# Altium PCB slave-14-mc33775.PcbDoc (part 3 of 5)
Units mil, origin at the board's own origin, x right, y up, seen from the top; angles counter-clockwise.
Board outline 6299.21 x 3937.01 mil, 6 copper layers (Top Copper, Supply, Signal Layer 1, Signal Layer 2, GND, Bot Copper), stack 69.773 mil thick; 428 components, 213 nets, 1149 pads, 1672 vias.
Unrouted connection lines stored in the file: 1.
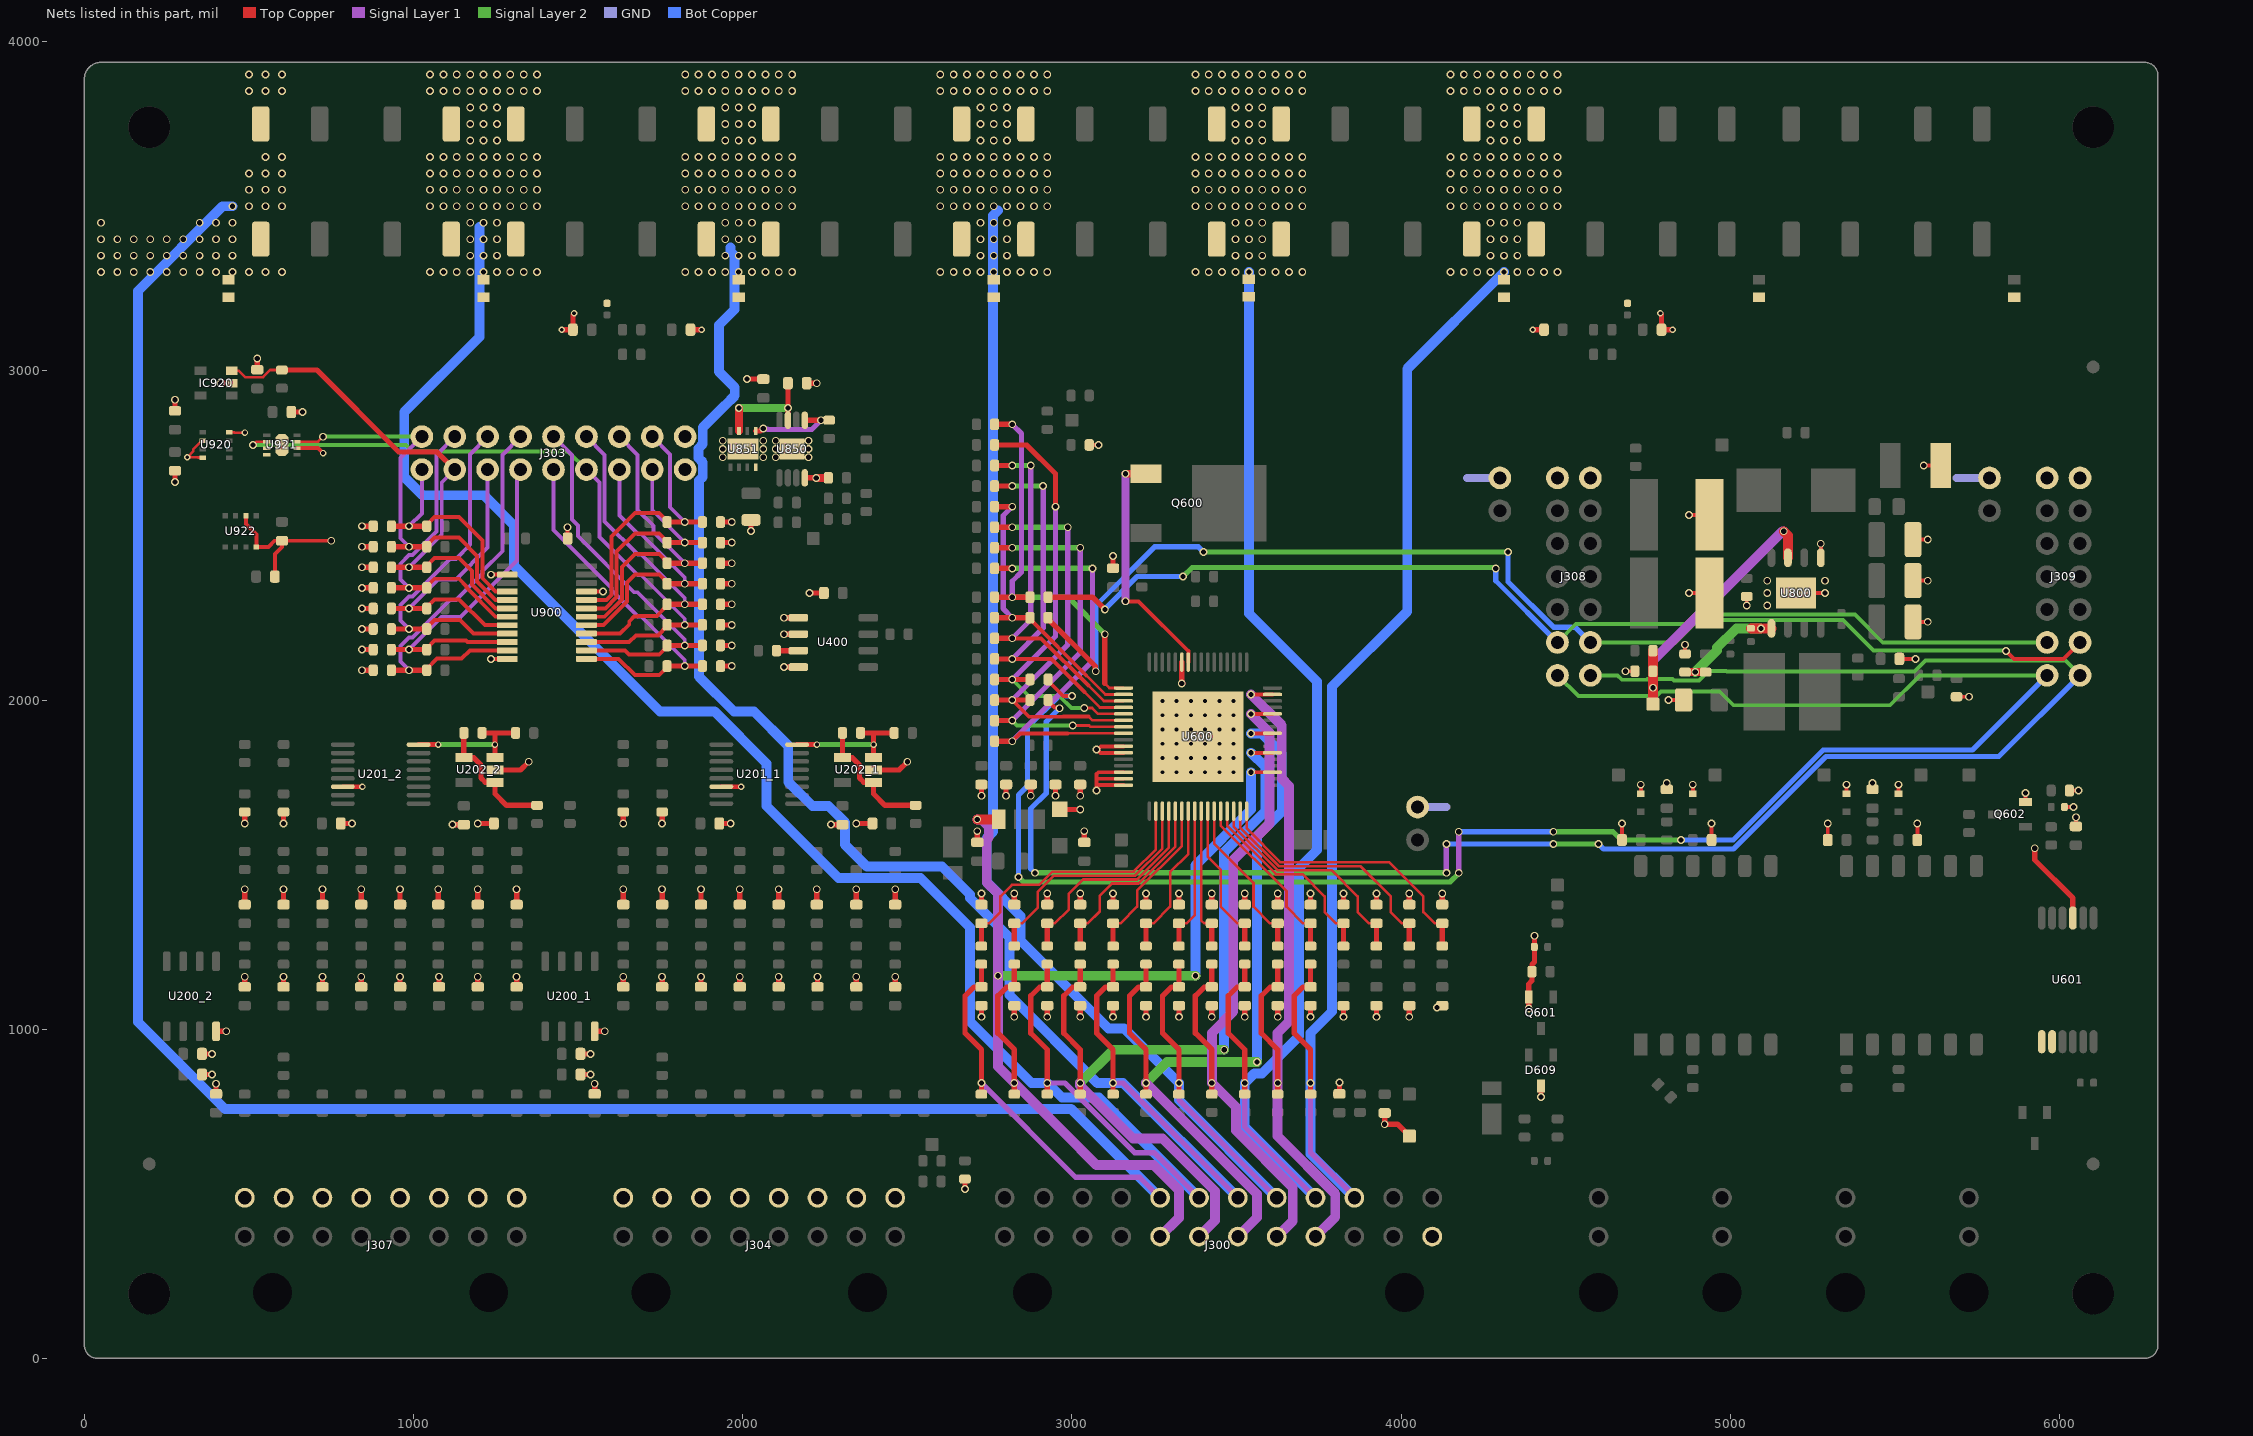
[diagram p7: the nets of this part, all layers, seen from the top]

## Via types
v1: diameter 23.62, hole 15.75, Top Copper to Bot Copper, 1585 vias
v2: diameter 19.68, hole 11.81, Top Copper to Bot Copper, 87 vias

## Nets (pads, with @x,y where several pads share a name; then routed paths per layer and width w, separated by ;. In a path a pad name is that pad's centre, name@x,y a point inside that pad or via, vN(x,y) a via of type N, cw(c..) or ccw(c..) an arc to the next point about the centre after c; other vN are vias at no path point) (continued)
CIN4: C510.2 J300.15 R505.2 R516.1 R708.1 R717.1 R718.2 R731.1 R732.2 | length 3963.7
  Top Copper w16: R516.1@3725,802.56 v1(3725,836.52) 3725,938.04 3675,988.04 3675,1101.24 3702.3,1128.54 C510.2@3725,1128.54 R505.2@3725,1197.44
  Signal Layer 1 w16: v1(3725,836.52) 3725,625 3857.99,492.01 J300.15@3857.99,487.99
  Bot Copper w30: J300.15@3857.99,487.99 3725,620.98 3725,988.27 3790.19,1053.46 3790.19,2040.96 4018.75,2269.52 4018.75,3006.25 v1(4312.5,3300)
  other v1: 4150,3300 4190.62,3300 4231.25,3300 4271.87,3300 4353.12,3300 4393.75,3300 4434.37,3300 4475,3300 4271.87,3350 4312.5,3350 4353.12,3350 4271.87,3400 4312.5,3400 4353.12,3400 4271.87,3450 4312.5,3450 4353.12,3450 4150,3500 4190.62,3500 4231.25,3500 4271.87,3500 4312.5,3500 4353.12,3500 4393.75,3500 4434.37,3500 4475,3500 4150,3550 4190.62,3550 4231.25,3550 4271.87,3550 4312.5,3550 4353.12,3550 4393.75,3550 4434.37,3550 4475,3550 4150,3600 4190.62,3600 4231.25,3600 4271.87,3600 4312.5,3600 4353.12,3600 4393.75,3600 4434.37,3600 4475,3600 4150,3650 4190.62,3650 4231.25,3650 4271.87,3650 4312.5,3650 4353.12,3650 4393.75,3650 4434.37,3650 4475,3650 4271.87,3700 4312.5,3700 4353.12,3700 4271.87,3750 4312.5,3750 4353.12,3750 4271.87,3800 4312.5,3800 4353.12,3800 4150,3850 4190.62,3850 4231.25,3850 4271.87,3850 4312.5,3850 4353.12,3850 4393.75,3850 4434.37,3850 4475,3850 4150,3900 4190.62,3900 4231.25,3900 4271.87,3900 4312.5,3900 4353.12,3900 4393.75,3900 4434.37,3900 4475,3900
CIN5: C506.2 J300.4 R503.2 R517.1 U600.31 | length 2319.5
  Top Copper w12: v1@3545.96,2016.83 U600.31@3609.35,2016.83
  Top Copper w16: R517.1@3625,802.56 v1(3625,836.52) 3625,938.04 3575,988.04 3575,1101.24 3602.3,1128.54 C506.2@3625,1128.54 R503.2@3625,1197.44
  Signal Layer 1 w30: v1(3544.09,2016.83) 3637.5,1923.43 3637.5,1761.7 3659.81,1739.39 3659.81,1023.08 3625,988.27 v1(3625,836.52) 3625,675 3800,500 3800,430 J300.4@3740,370
CIN6: C502.2 J300.16 R501.2 R518.1 R709.1 R719.1 R720.2 R733.1 R734.2 | length 3978.9
  Top Copper w16: R518.1@3525,802.56 v1(3525,836.52) 3525,938.04 3475,988.04 3475,1101.24 3502.3,1128.54 C502.2@3525,1128.54 R501.2@3525,1197.44
  Signal Layer 1 w16: v1(3525,836.52) 3525,702.99 J300.16@3740,487.99
  Bot Copper w30: v1(3537.5,3300) 3537.5,2263.27 3745,2055.77 3745,1544.52 3690.19,1489.71 3690.19,978.46 3576.92,865.19 3553.67,865.19 v1(3525,836.52) 3525,702.99 J300.16@3740,487.99
  other v1: 3375,3300 3415.62,3300 3456.25,3300 3496.87,3300 3578.12,3300 3618.75,3300 3659.37,3300 3700,3300 3496.87,3350 3537.5,3350 3578.12,3350 3496.87,3400 3537.5,3400 3578.12,3400 3496.87,3450 3537.5,3450 3578.12,3450 3375,3500 3415.62,3500 3456.25,3500 3496.87,3500 3537.5,3500 3578.12,3500 3618.75,3500 3659.37,3500 3700,3500 3375,3550 3415.62,3550 3456.25,3550 3496.87,3550 3537.5,3550 3578.12,3550 3618.75,3550 3659.37,3550 3700,3550 3375,3600 3415.62,3600 3456.25,3600 3496.87,3600 3537.5,3600 3578.12,3600 3618.75,3600 3659.37,3600 3700,3600 3375,3650 3415.62,3650 3456.25,3650 3496.87,3650 3537.5,3650 3578.12,3650 3618.75,3650 3659.37,3650 3700,3650 3496.87,3700 3537.5,3700 3578.12,3700 3496.87,3750 3537.5,3750 3578.12,3750 3496.87,3800 3537.5,3800 3578.12,3800 3375,3850 3415.62,3850 3456.25,3850 3496.87,3850 3537.5,3850 3578.12,3850 3618.75,3850 3659.37,3850 3700,3850 3375,3900 3415.62,3900 3456.25,3900 3496.87,3900 3537.5,3900 3578.12,3900 3618.75,3900 3659.37,3900 3700,3900
CIN7: C528.2 J300.5 R514.2 R519.1 U600.28 | length 2319.5
  Top Copper w12: v1@3545.96,1957.78 U600.28@3609.35,1957.78
  Top Copper w16: R519.1@3425,802.56 v1(3425,836.52) 3425,938.04 3375,988.04 3375,1101.24 3402.3,1128.54 C528.2@3425,1128.54 R514.2@3425,1197.44
  Signal Layer 1 w30: v1(3544.09,1957.78) 3600,1901.87 3600,1624.23 3490.19,1514.42 3490.19,1053.46 3425,988.27 v1(3425,836.52) 3498,763.52 3498,691.81 3671.01,518.8 3671.01,417.42 3623.59,370 J300.5@3622.01,370
CIN8: C524.2 J300.17 R512.2 R520.1 R710.1 R721.1 R722.2 R735.1 R736.2 | length 4327.7
  Top Copper w16: R520.1@3325,802.56 v1(3325,836.52) 3325,938.04 3275,988.04 3275,1101.24 3302.3,1128.54 C524.2@3325,1128.54 R512.2@3325,1197.44
  Signal Layer 1 w16: v1(3325,836.52) 3325,785 J300.17@3622.01,487.99
  Bot Copper w30: 2775,3487.5 2759.81,3472.31 2759.81,1599.75 2741.27,1581.21 2741.27,1447 2843.81,1344.46 2843.81,1269.46 3110.58,1002.69 3158.83,1002.69 v1(3325,836.52) 3325,785 J300.17@3622.01,487.99
  other v1: 2600,3300 2640.62,3300 2681.25,3300 2721.87,3300 2762.5,3300 2803.12,3300 2843.75,3300 2884.37,3300 2925,3300 2721.87,3350 2762.5,3350 2803.12,3350 2721.87,3400 2762.5,3400 2803.12,3400 2721.87,3450 2762.5,3450 2803.12,3450 2600,3500 2640.62,3500 2681.25,3500 2721.87,3500 2762.5,3500 2803.12,3500 2843.75,3500 2884.37,3500 2925,3500 2600,3550 2640.62,3550 2681.25,3550 2721.87,3550 2762.5,3550 2803.12,3550 2843.75,3550 2884.37,3550 2925,3550 2600,3600 2640.62,3600 2681.25,3600 2721.87,3600 2762.5,3600 2803.12,3600 2843.75,3600 2884.37,3600 2925,3600 2600,3650 2640.62,3650 2681.25,3650 2721.87,3650 2762.5,3650 2803.12,3650 2843.75,3650 2884.37,3650 2925,3650 2721.87,3700 2762.5,3700 2803.12,3700 2721.87,3750 2762.5,3750 2803.12,3750 2721.87,3800 2762.5,3800 2803.12,3800 2600,3850 2640.62,3850 2681.25,3850 2721.87,3850 2762.5,3850 2803.12,3850 2843.75,3850 2884.37,3850 2925,3850 2600,3900 2640.62,3900 2681.25,3900 2721.87,3900 2762.5,3900 2803.12,3900 2843.75,3900 2884.37,3900 2925,3900
CIN9: C520.2 J300.6 R510.2 R521.1 U600.25 | length 2594.7
  Top Copper w12: v1@3545.96,1898.72 U600.25@3609.35,1898.72
  Top Copper w16: R521.1@3225,802.56 v1(3225,836.52) 3225,938.04 3175,988.04 3175,1101.24 3202.3,1128.54 C520.2@3225,1128.54 R510.2@3225,1197.44
  Signal Layer 1 w30: v1(3225,836.52) 3562.5,499.02 3562.5,428.48 J300.6@3504.02,370
  Signal Layer 2 w30: v1(3225,836.52) 3288.48,900 v1(3562.5,900)
  Bot Copper w30: v1(3544.09,1898.72) 3576.28,1898.72 3637.5,1837.5 3637.5,1661.73 3562.5,1586.73 v1(3562.5,900)
CIN10: C516.2 J300.18 R508.2 R522.1 R711.1 R723.1 R724.2 R737.1 R738.2 | length 4883.5
  Top Copper w16: R522.1@3125,802.56 v1(3125,836.52) 3125,938.04 3075,988.04 3075,1101.24 3102.3,1128.54 C516.2@3125,1128.54 R508.2@3125,1197.44
  Signal Layer 1 w16: v1(3125,836.52) 3155.49,836.52 J300.18@3504.02,487.99
  Bot Copper w30: 1962.5,3375 1962.5,3362.5 1975,3350 1975,3300 1975,3186.73 1927.69,3139.42 1927.69,2997.13 1975.66,2949.16 1975.66,2924.3 1945.77,2894.41 1945.08,2894.41 1878.45,2827.78 1878.45,2777.86 1865.19,2764.6 1865.19,2735.58 1878.45,2722.32 1878.45,2677.86 1867.35,2666.76 1867.35,2070.92 1973.08,1965.19 2034.04,1965.19 2138.16,1861.07 2138.16,1751.42 2211.4,1678.18 2260.62,1678.18 2310.19,1628.61 2310.19,1560.29 2376.66,1493.81 2605.42,1493.81 2690.19,1409.04 2690.19,1398.08 2809.81,1278.46 2809.81,1103.46 3076.75,836.52 v1(3125,836.52) 3155.49,836.52 J300.18@3504.02,487.99
  other v1: 1825,3300 1865.62,3300 1906.25,3300 1946.87,3300 1987.5,3300 2028.12,3300 2068.75,3300 2109.37,3300 2150,3300 1946.87,3350 1987.5,3350 2028.12,3350 1946.87,3400 1987.5,3400 2028.12,3400 1946.87,3450 1987.5,3450 2028.12,3450 1825,3500 1865.62,3500 1906.25,3500 1946.87,3500 1987.5,3500 2028.12,3500 2068.75,3500 2109.37,3500 2150,3500 1825,3550 1865.62,3550 1906.25,3550 1946.87,3550 1987.5,3550 2028.12,3550 2068.75,3550 2109.37,3550 2150,3550 1825,3600 1865.62,3600 1906.25,3600 1946.87,3600 1987.5,3600 2028.12,3600 2068.75,3600 2109.37,3600 2150,3600 1825,3650 1865.62,3650 1906.25,3650 1946.87,3650 1987.5,3650 2028.12,3650 2068.75,3650 2109.37,3650 2150,3650 1946.87,3700 1987.5,3700 2028.12,3700 1946.87,3750 1987.5,3750 2028.12,3750 1946.87,3800 1987.5,3800 2028.12,3800 1825,3850 1865.62,3850 1906.25,3850 1946.87,3850 1987.5,3850 2028.12,3850 2068.75,3850 2109.37,3850 2150,3850 1825,3900 1865.62,3900 1906.25,3900 1946.87,3900 1987.5,3900 2028.12,3900 2068.75,3900 2109.37,3900 2150,3900
CIN11: C512.2 J300.7 R506.2 R523.1 U600.22 | length 2673.7
  Top Copper w12: v1@3545.96,1839.67 U600.22@3609.35,1839.67
  Top Copper w16: R523.1@3025,802.56 v1(3025,836.52) 3025,938.04 2975,988.04 2975,1101.24 3002.3,1128.54 C512.2@3025,1128.54 R506.2@3025,1197.44
  Signal Layer 1 w30: v1(3025,836.52) 3025,828.56 3185.14,668.43 3274.85,668.43 3434.98,508.29 3434.98,418.53 3386.45,370 J300.7@3385.98,370
  Signal Layer 2 w30: v1(3025,836.52) 3125.98,937.5 v1(3462.5,937.5)
  Bot Copper w30: v1(3462.5,937.5) 3462.5,1537.5 3587.5,1662.5 3587.5,1796.26 v1(3544.09,1839.67)
CIN12: C508.2 J300.19 R504.2 R524.1 R712.1 R725.1 R726.2 R739.1 R740.2 | length 5546
  Top Copper w16: R524.1@2925,802.56 v1(2925,836.52) 2925,938.04 2875,988.04 2875,1101.24 2902.3,1128.54 C508.2@2925,1128.54 R504.2@2925,1197.44
  Signal Layer 1 w16: v1(2925,836.52) 2978.87,836.52 3190.38,625 3248.98,625 J300.19@3385.98,487.99
  Bot Copper w30: 1200,3437.5 1200,3103.15 971.56,2874.71 971.56,2677.86 1027.11,2622.31 1213.61,2622.31 1305.15,2530.77 1305.15,2408.12 1748.08,1965.19 1914.92,1965.19 2072.47,1807.64 2072.47,1678 2290.66,1459.81 2539.42,1459.81 2690.19,1309.04 2690.19,1023.08 2876.75,836.52 v1(2925,836.52) 2969.45,792.07 3081.91,792.07 J300.19@3385.98,487.99
  other v1: 1050,3300 1090.62,3300 1131.25,3300 1171.87,3300 1212.5,3300 1253.12,3300 1293.75,3300 1334.37,3300 1375,3300 1171.87,3350 1212.5,3350 1253.12,3350 1171.87,3400 1212.5,3400 1253.12,3400 1171.87,3450 1212.5,3450 1253.12,3450 1050,3500 1090.62,3500 1131.25,3500 1171.87,3500 1212.5,3500 1253.12,3500 1293.75,3500 1334.37,3500 1375,3500 1050,3550 1090.62,3550 1131.25,3550 1171.87,3550 1212.5,3550 1253.12,3550 1293.75,3550 1334.37,3550 1375,3550 1050,3600 1090.62,3600 1131.25,3600 1171.87,3600 1212.5,3600 1253.12,3600 1293.75,3600 1334.37,3600 1375,3600 1050,3650 1090.62,3650 1131.25,3650 1171.87,3650 1212.5,3650 1253.12,3650 1293.75,3650 1334.37,3650 1375,3650 1171.87,3700 1212.5,3700 1253.12,3700 1171.87,3750 1212.5,3750 1253.12,3750 1171.87,3800 1212.5,3800 1253.12,3800 1050,3850 1090.62,3850 1131.25,3850 1171.87,3850 1212.5,3850 1253.12,3850 1293.75,3850 1334.37,3850 1375,3850 1050,3900 1090.62,3900 1131.25,3900 1171.87,3900 1212.5,3900 1253.12,3900 1293.75,3900 1334.37,3900 1375,3900
CIN13: C504.2 D603.2 J300.8 R502.2 R525.1 U600.19 | length 3525.9
  Top Copper w12: v1@3545.96,1780.61 U600.19@3609.35,1780.61
  Top Copper w16: R525.1@2825,802.56 v1(2825,836.52) 2825,938.04 2775,988.04 2775,1101.24 2802.3,1128.54 C504.2@2825,1128.54 R502.2@2825,1197.44
  Top Copper w30: v1(2712.5,1637.5) D603.2@2777.46,1637.5
  Signal Layer 1 w30: v1(2712.5,1637.5) 2713.52,1636.48 2726.92,1636.48 2747.31,1616.09 2747.31,1582.96 2741.27,1576.92 2741.27,1445.46 2775,1411.73 v1(2775,1162.5) 2775,886.52 v1(2825,836.52) 2975.78,685.73 3074.02,587.5 3248.29,587.5 3325,510.79 3325,427.01 J300.8@3267.99,370
  Signal Layer 2 w30: v1(2775,1162.5) v1(3375,1162.5)
  Bot Copper w30: v1(3375,1162.5) 3375,1498.08 3544.09,1667.18 v1(3544.09,1780.61)
CIN14: C500.2 J300.20 R500.2 R526.1 R713.1 R727.2 R741.2 | length 7078.1
  Top Copper w16: R526.1@2725,802.56 v1(2725,836.52) 2725,938.04 2675,988.04 2675,1101.24 2702.3,1128.54 C500.2@2725,1128.54 R500.2@2725,1197.44
  Signal Layer 1 w16: v1(2725,836.52) 3011.52,550 3205.98,550 J300.20@3267.99,487.99
  Bot Copper w30: v1(450,3500) 419.66,3500 162.61,3242.96 162.61,1022.41 426.95,758.07 2997.91,758.07 J300.20@3267.99,487.99
  other v1: 50,3300 100,3300 150,3300 200,3300 250,3300 300,3300 350,3300 400,3300 450,3300 500,3300 550,3300 600,3300 50,3350 100,3350 150,3350 200,3350 250,3350 300,3350 350,3350 400,3350 450,3350 50,3400 100,3400 150,3400 200,3400 250,3400 300,3400 350,3400 400,3400 450,3400 50,3450 350,3450 400,3450 450,3450 500,3500 550,3500 600,3500 500,3550 550,3550 600,3550 500,3600 550,3600 600,3600 550,3650 600,3650 500,3850 550,3850 600,3850 500,3900 550,3900 600,3900
CT0: C527.2 R513.1 U600.16 | length 862.7
  Top Copper w8: U600.16@3530.61,1662.5 3530.61,1610.72 3634.29,1507.03 3964.14,1507.03 4067.83,1403.35 4067.83,1355.93 4102.3,1321.46 C527.2@4125,1321.46
  Top Copper w16: R513.1@4125,1252.56 C527.2@4125,1321.46
CT1: C523.2 R511.1 U600.15 | length 780.8
  Top Copper w8: U600.15@3510.93,1662.5 3510.93,1613.43 3629.32,1495.03 3876.14,1495.03 3968.58,1402.59 3968.58,1355.17 4002.3,1321.46 C523.2@4025,1321.46
  Top Copper w16: R511.1@4025,1252.56 C523.2@4025,1321.46
CT2: C519.2 R509.1 U600.14 | length 698.9
  Top Copper w8: U600.14@3491.24,1662.5 3491.24,1616.14 3624.35,1483.03 3788.14,1483.03 3867.74,1403.44 3867.74,1356.02 3902.3,1321.46 C519.2@3925,1321.46
  Top Copper w16: R509.1@3925,1252.56 C519.2@3925,1321.46
CT3: C515.2 R507.1 U600.13 | length 616.9
  Top Copper w8: U600.13@3471.56,1662.5 3471.56,1618.86 3619.38,1471.03 3700.14,1471.03 3767.74,1403.44 3767.74,1356.02 3802.3,1321.46 C515.2@3825,1321.46
  Top Copper w16: R507.1@3825,1252.56 C515.2@3825,1321.46
CT4: C511.2 R505.1 U600.12 | length 536.4
  Top Copper w8: U600.12@3451.87,1662.5 3451.87,1619.3 3651.7,1419.47 3651.7,1372.06 3702.3,1321.46 C511.2@3725,1321.46
  Top Copper w16: R505.1@3725,1252.56 C511.2@3725,1321.46
CT5: C507.2 R503.1 U600.11 | length 503.1
  Top Copper w8: U600.11@3432.19,1662.5 3432.19,1564.32 3551.7,1444.81 3551.7,1372.06 3602.3,1321.46 C507.2@3625,1321.46
  Top Copper w16: R503.1@3625,1252.56 C507.2@3625,1321.46
CT6: C503.2 R501.1 U600.10 | length 469.8
  Top Copper w8: U600.10@3412.5,1662.5 3412.5,1524.16 3451.7,1484.96 3451.7,1372.06 3502.3,1321.46 C503.2@3525,1321.46
  Top Copper w16: R501.1@3525,1252.56 C503.2@3525,1321.46
CT7: C529.2 R514.1 U600.9 | length 436.6
  Top Copper w8: U600.9@3392.82,1662.5 3392.82,1330.94 3402.3,1321.46 C529.2@3425,1321.46
  Top Copper w16: R514.1@3425,1252.56 C529.2@3425,1321.46
CT8: C525.2 R512.1 U600.8 | length 443.2
  Top Copper w8: C525.2@3325,1321.46 3347.7,1321.46 3373.13,1346.89 U600.8@3373.13,1662.5
  Top Copper w16: R512.1@3325,1252.56 C525.2@3325,1321.46
CT9: C521.2 R510.1 U600.7 | length 476.4
  Top Copper w8: C521.2@3225,1321.46 3247.7,1321.46 3298.3,1372.06 3298.3,1476.99 3353.44,1532.14 U600.7@3353.44,1662.5
  Top Copper w16: R510.1@3225,1252.56 C521.2@3225,1321.46
CT10: C517.2 R508.1 U600.6 | length 509.7
  Top Copper w8: C517.2@3125,1321.46 3147.7,1321.46 3198.3,1372.06 3198.3,1421.74 3333.76,1557.2 U600.6@3333.76,1662.5
  Top Copper w16: R508.1@3125,1252.56 C517.2@3125,1321.46
CT11: C513.2 R506.1 U600.5 | length 590.3
  Top Copper w8: C513.2@3025,1321.46 3047.7,1321.46 3084.57,1358.33 3084.57,1405.74 3121.44,1442.61 3202.2,1442.61 3314.07,1554.49 U600.5@3314.07,1662.5
  Top Copper w16: R506.1@3025,1252.56 C513.2@3025,1321.46
CT12: C509.2 R504.1 U600.4 | length 672.2
  Top Copper w8: C509.2@2925,1321.46 2947.7,1321.46 2990.57,1364.33 2990.57,1411.74 3033.44,1454.61 3197.23,1454.61 3294.39,1551.78 U600.4@3294.39,1662.5
  Top Copper w16: R504.1@2925,1252.56 C509.2@2925,1321.46
CT13: C505.2 R502.1 U600.3 | length 754.1
  Top Copper w8: C505.2@2825,1321.46 2847.7,1321.46 2896.57,1370.33 2896.57,1417.74 2945.44,1466.61 3192.26,1466.61 3274.7,1549.06 U600.3@3274.7,1662.5
  Top Copper w16: R502.1@2825,1252.56 C505.2@2825,1321.46
CT14: C501.2 R500.1 U600.2 | length 836
  Top Copper w8: C501.2@2725,1321.46 2747.7,1321.46 2782.61,1356.36 2782.61,1403.78 2817.52,1438.69 2900.54,1438.69 2940.47,1478.61 3187.29,1478.61 3255.02,1546.35 U600.2@3255.02,1662.5
  Top Copper w16: R500.1@2725,1252.56 C501.2@2725,1321.46
D_1: R230_1.1 R232_1.1 U201_1.8 U202_1.3 | length 410.4
  Top Copper w15: U201_1.8@2165.16,1864.57 v2(2225,1864.57) ; R232_1.1@2357.87,1900 2400,1900 ; U202_1.3@2397.24,1824.9 v2(2397.24,1864.57) 2397.24,1897.24 2400,1900 ; R230_1.1@2459.94,1900 2400,1900
  Signal Layer 2 w15: v2(2225,1864.57) v2(2397.24,1864.57)
D_2: R230_2.1 R232_2.1 U201_2.8 U202_2.3 | length 410.4
  Top Copper w15: U201_2.8@1015.16,1864.57 v2(1075,1864.57) ; R232_2.1@1207.87,1900 1250,1900 ; U202_2.3@1247.24,1824.9 v2(1247.24,1864.57) 1247.24,1897.24 1250,1900 ; R230_2.1@1309.94,1900 1250,1900
  Signal Layer 2 w15: v2(1075,1864.57) v2(1247.24,1864.57)
D_amp_1: R231_1.1 R232_1.2 U202_1.1 U202_1.4 | length 403.6
  Top Copper w16: R232_1.2@2302.76,1900 U202_1.4@2302.76,1824.9 2332.35,1824.9 2354.69,1802.56 2354.69,1763.07 2367.65,1750.1 U202_1.1@2400,1750.1 ; U202_1.1@2397.24,1750.1 2397.24,1715.26 2432.38,1680.12 R231_1.1@2525,1680.12
D_amp_2: R231_2.1 R232_2.2 U202_2.1 U202_2.4 | length 403.6
  Top Copper w16: R232_2.2@1152.76,1900 U202_2.4@1152.76,1824.9 1182.35,1824.9 1204.69,1802.56 1204.69,1763.07 1217.65,1750.1 U202_2.1@1250,1750.1 ; U202_2.1@1247.24,1750.1 1247.24,1715.26 1282.38,1680.12 R231_2.1@1375,1680.12
Delay_LDO: C852.2 U850.7 U851.7 | length 331.7
  Top Copper w16: U850.7@2137.2,2850.1 C852.2@2137.2,2962.5
  Top Copper w24: U851.7@1988.09,2817.62 v1(1988.09,2887.5)
  Signal Layer 2 w24: v1(1988.09,2887.5) v1(2137.5,2887.5)
DIGITAL-IO_0: J303.1 R910.1 R917.2 U900.4 | length 714.8
  Top Copper w12: R910.1@1039.86,2528.25 1039.86,2532.19 1063.64,2555.96 1137.72,2555.96 1209.03,2484.66 1209.03,2370.04 1249.35,2329.72 U900.4@1284.84,2329.72
  Top Copper w16: R917.2@932.48,2528.25 v1(986.17,2528.25) R910.1@1039.86,2528.25
  Signal Layer 1 w12: v1(986.17,2528.25) 1025.01,2567.08 J303.1@1025.01,2700
DIGITAL-IO_1: J303.2 R900.1 R924.2 U900.5 U921.3 | length 1247
  Top Copper w8: U921.3@646.06,2784.84 709.84,2784.84 v1(725,2800)
  Top Copper w12: R900.1@1039.86,2465.75 1039.86,2469.69 1063.64,2493.46 1137.72,2493.46 1193.03,2438.16 1193.03,2360.45 1249.35,2304.13 U900.5@1284.84,2304.13
  Top Copper w16: R924.2@932.48,2465.75 v1(986.17,2465.75) R900.1@1039.86,2465.75
  Signal Layer 1 w12: v1(986.17,2465.75) 960.36,2491.56 960.36,2735.35 J303.2@1025.01,2800
  Signal Layer 2 w12: v1(725,2800) J303.2@1025.01,2800
DIGITAL-IO_2: IC920.3 J303.3 R905.1 R920.1 R929.2 U900.6 | length 1627.5
  Top Copper w8: IC920.3@447.24,2999.9 468.96,2999.9 488.08,2980.78 542.69,2980.78 564.47,3002.56 R920.1@600,3002.56
  Top Copper w12: R905.1@1039.86,2403.25 1039.86,2407.19 1063.64,2430.96 1137.72,2430.96 1177.03,2391.66 1177.03,2350.86 1249.35,2278.54 U900.6@1284.84,2278.54
  Top Copper w16: R920.1@600,3002.56 706.03,3002.56 955.04,2753.55 1071.45,2753.55 J303.3@1125,2700 ; R929.2@932.48,2403.25 v1(986.17,2403.25) R905.1@1039.86,2403.25
  Signal Layer 1 w12: v1(986.17,2403.25) 1085.46,2502.53 1085.46,2660.46 J303.3@1125,2700
DIGITAL-IO_3: J303.4 R911.1 R918.2 U900.7 | length 960.6
  Top Copper w12: R911.1@1039.86,2340.75 1039.86,2344.69 1063.64,2368.46 1137.72,2368.46 1161.03,2345.16 1161.03,2341.27 1249.35,2252.95 U900.7@1284.84,2252.95
  Top Copper w16: R918.2@932.48,2340.75 v1(986.17,2340.75) R911.1@1039.86,2340.75
  Signal Layer 1 w12: v1(986.17,2340.75) 960.36,2366.56 960.36,2413.94 986.36,2439.94 996.86,2439.94 1069.46,2512.53 1069.46,2744.46 J303.4@1125,2800
DIGITAL-IO_4: J303.5 R901.1 R925.2 U900.8 | length 951.2
  Top Copper w12: R901.1@1039.86,2278.25 1039.86,2282.19 1063.64,2305.96 1137.72,2305.96 1216.32,2227.36 U900.8@1284.84,2227.36
  Top Copper w16: R925.2@932.48,2278.25 v1(986.17,2278.25) R901.1@1039.86,2278.25
  Signal Layer 1 w12: v1(986.17,2278.25) 1074.48,2366.56 1128.75,2366.56 1225,2462.81 J303.5@1225,2700
DIGITAL-IO_5: J303.6 R906.1 R930.2 U900.9 | length 1104.5
  Top Copper w12: R906.1@1039.86,2215.75 1039.86,2219.69 1063.64,2243.46 1140.65,2243.46 1182.34,2201.77 U900.9@1284.84,2201.77
  Top Copper w16: R930.2@932.48,2215.75 v1(986.17,2215.75) R906.1@1039.86,2215.75
  Signal Layer 1 w12: v1(986.17,2215.75) 960.36,2241.56 960.36,2288.94 986.36,2314.94 996.86,2314.94 1110.98,2429.06 1128.75,2429.06 1171.43,2471.74 1171.43,2746.43 J303.6@1225,2800
DIGITAL-IO_6: J303.7 R912.1 R919.2 U900.10 | length 1088.9
  Top Copper w12: R912.1@1039.86,2153.25 1039.86,2157.19 1063.64,2180.96 1159.1,2180.96 1163.89,2176.18 U900.10@1284.84,2176.18
  Top Copper w16: R919.2@932.48,2153.25 v1(986.17,2153.25) R912.1@1039.86,2153.25
  Signal Layer 1 w12: v1(986.17,2153.25) 1085.36,2252.44 1142.88,2252.44 1314.15,2423.71 1314.15,2689.15 J303.7@1325,2700
DIGITAL-IO_7: J303.8 R902.1 R926.2 U900.11 | length 1267.2
  Top Copper w12: R902.1@1039.86,2090.75 1039.86,2094.69 1070.71,2125.53 1145.48,2125.53 1170.76,2150.81 1245.53,2150.81 1245.75,2150.59 U900.11@1284.84,2150.59
  Top Copper w16: R926.2@932.48,2090.75 v1(986.17,2090.75) R902.1@1039.86,2090.75
  Signal Layer 1 w12: v1(986.17,2090.75) 960.36,2116.56 960.36,2163.94 986.36,2189.94 996.86,2189.94 1110.98,2304.06 1128.75,2304.06 1209.03,2384.34 1209.03,2391.6 1269.45,2452.01 1269.45,2744.45 J303.8@1325,2800
DIGITAL-IO_8: J303.9 R907.1 R931.2 U900.13 | length 1154.7
  Top Copper w12: U900.13@1525,2125 1622.65,2125 1672.12,2075.53 1746.2,2075.53 1769.98,2099.31 R907.1@1769.98,2103.25
  Top Copper w16: R907.1@1769.98,2103.25 v1(1823.67,2103.25) R931.2@1877.36,2103.25
  Signal Layer 1 w12: J303.9@1425,2700 1425,2516.23 1600.81,2340.42 1600.81,2334.34 1681.09,2254.06 1691.6,2254.06 1823.67,2121.98 v1(1823.67,2103.25)
DIGITAL-IO_9: J303.10 R913.1 R921.2 U900.14 | length 1176.9
  Top Copper w12: U900.14@1525,2150.59 1642.07,2150.59 1654.63,2138.03 1746.2,2138.03 1769.98,2161.81 R913.1@1769.98,2165.75
  Top Copper w16: R913.1@1769.98,2165.75 v1(1823.67,2165.75) R921.2@1877.36,2165.75
  Signal Layer 1 w12: J303.10@1425,2800 1480.55,2744.45 1480.55,2548.57 1499.19,2529.93 1499.19,2498.46 1670.21,2327.44 1680.72,2327.44 1823.67,2184.48 v1(1823.67,2165.75)
DIGITAL-IO_10: J303.11 R903.1 R927.2 U900.15 U921.6 | length 2066.9
  Top Copper w8: v1(512.5,2775) 522.34,2784.84 U921.6@553.94,2784.84
  Top Copper w12: U900.15@1525,2176.18 1654.84,2176.18 1675.17,2196.51 1742.18,2196.51 1769.98,2224.31 R903.1@1769.98,2228.25
  Top Copper w16: R903.1@1769.98,2228.25 v1(1823.67,2228.25) R927.2@1877.36,2228.25
  Signal Layer 1 w12: J303.11@1525,2700 1564.55,2660.45 1564.55,2495.6 1681.09,2379.06 1691.6,2379.06 1823.67,2246.98 v1(1823.67,2228.25)
  Signal Layer 2 w12: v1(512.5,2775) 513.31,2774.19 976.47,2774.19 995.11,2755.55 1469.45,2755.55 J303.11@1525,2700
DIGITAL-IO_11: J303.12 R908.1 R932.2 U900.16 | length 1035.8
  Top Copper w12: U900.16@1525,2201.77 1626.77,2201.77 1655.09,2230.09 1655.09,2238.94 1670.21,2254.06 1679.06,2254.06 1680.96,2255.96 1739.13,2255.96 1769.98,2286.81 R908.1@1769.98,2290.75
  Top Copper w16: R908.1@1769.98,2290.75 v1(1823.67,2290.75) R932.2@1877.36,2290.75
  Signal Layer 1 w12: J303.12@1525,2800 1580.55,2744.45 1580.55,2542.1 1681.09,2441.56 1691.6,2441.56 1823.67,2309.48 v1(1823.67,2290.75)
DIGITAL-IO_12: J303.13 R914.1 R922.2 U900.17 | length 899.2
  Top Copper w12: U900.17@1525,2227.36 1577.02,2227.36 1648.81,2299.15 1648.81,2357.66 1672.12,2380.96 1746.2,2380.96 1769.98,2357.19 R914.1@1769.98,2353.25
  Top Copper w16: R914.1@1769.98,2353.25 v1(1823.67,2353.25) R922.2@1877.36,2353.25
  Signal Layer 1 w12: J303.13@1625,2700 1625,2560.15 1681.09,2504.06 1691.6,2504.06 1823.67,2371.98 v1(1823.67,2353.25)
DIGITAL-IO_13: J303.14 R904.1 R928.2 U900.18 | length 969.2
  Top Copper w12: U900.18@1525,2252.95 1579.99,2252.95 1632.81,2305.78 1632.81,2404.16 1672.12,2443.46 1746.2,2443.46 1769.98,2419.69 R904.1@1769.98,2415.75
  Top Copper w16: R904.1@1769.98,2415.75 v1(1823.67,2415.75) R928.2@1877.36,2415.75
  Signal Layer 1 w12: J303.14@1625,2800 1680.55,2744.45 1680.55,2577.6 1728.67,2529.49 1728.67,2510.75 v1(1823.67,2415.75)
DIGITAL-IO_14: J303.15 R909.1 R933.2 U900.19 | length 804
  Top Copper w12: U900.19@1525,2278.54 1582.95,2278.54 1616.81,2312.41 1616.81,2450.66 1672.12,2505.96 1746.2,2505.96 1769.98,2482.19 R909.1@1769.98,2478.25
  Top Copper w16: R909.1@1769.98,2478.25 v1(1823.67,2478.25) R933.2@1877.36,2478.25
  Signal Layer 1 w12: J303.15@1725,2700 1725,2576.92 v1(1823.67,2478.25)
DIGITAL-IO_15: J303.16 R915.1 R923.2 U900.20 | length 880.3
  Top Copper w12: U900.20@1525,2304.13 1564.09,2304.13 1564.31,2303.91 1585.69,2303.91 1600.81,2319.03 1600.81,2497.16 1672.12,2568.46 1746.2,2568.46 1769.98,2544.69 R915.1@1769.98,2540.75
  Top Copper w16: R915.1@1769.98,2540.75 v1(1823.67,2540.75) R923.2@1877.36,2540.75
  Signal Layer 1 w12: J303.16@1725,2800 1778.67,2746.33 1778.67,2585.75 v1(1823.67,2540.75)
Drive_VDDC: Q600.1 U600.42 | length 737.1
  Top Copper w12: v1(3162.5,2300) 3202.23,2300 3353.44,2148.78 U600.42@3353.44,2115.26
  Top Copper w24: v1(3162.5,2687.5) Q600.1@3225,2687.5
  Signal Layer 1 w24: v1(3162.5,2300) v1(3162.5,2687.5)
E2: R401.1 U400.3 | length 66.1
  Top Copper w16: R401.1@2102.56,2150 U400.3@2168.7,2150
Enable_DCDC: enable_DCDC.1 R807.2 R810.1 U800.3 | length 890.3
  Top Copper w30: enable_DCDC.1@4765.06,1987.5 4765.06,2011.18 R807.2@4765.06,2150 ; v1(5162.5,2512.5) 5175,2500 U800.3@5175,2432.28
  Signal Layer 1 w30: v1(4765.06,2037.5) 4765.06,2119.74 5157.82,2512.5 v1(5162.5,2512.5)
Enable_LDO: R851.1 U850.5 U851.5 | length 288.1
  Top Copper w16: U851.5@2039.27,2817.62 2053.06,2817.62 2060.44,2825 v1(2062.5,2825) ; U850.5@2188.39,2850.1 R851.1@2262.5,2850.1
  Signal Layer 1 w16: v1(2062.5,2825) 2063.96,2823.54 2074.63,2823.54 2075.98,2822.19 2209.69,2822.19 v1(2237.5,2850)
Feedback: C809.1 R806.1 R808.2 U800.5 | length 384.7
  Top Copper w24: R808.2@4862.5,2084.94 4884.22,2084.94 v1(4893.75,2084.94) R806.1@4925,2084.94
  Top Copper w30: C809.1@5062.5,2217.72 v1(5093.75,2217.72) U800.5@5125,2217.72
  Signal Layer 2 w30: v1(4893.75,2084.94) 4959.81,2151 4959.81,2159.04 5018.49,2217.72 v1(5093.75,2217.72)
GND: C200_1.1 C200_2.1 C201_1.1 C201_2.1 C202_1.1 C202_2.1 C203_1.1 C203_2.1 C204_1.1 C204_2.1 C205_1.1 C205_2.1 C206_1.1 C206_2.1 C207_1.1 C207_2.1 C208_1.1 C208_2.1 C209_1.1 C209_2.1 C210_1.1 C210_2.1 C211_1.1 C211_2.1 C212_1.1 C212_2.1 C213_1.1 C213_2.1 C214_1.1 C214_2.1 C215_1.1 C215_2.1 C216_1.1 C216_2.1 C217_1.1 C217_2.1 C218_1.1 C218_2.1 C219_1.1 C219_2.1 C220_1.1 C220_2.1 C221_1.1 C221_2.1 C400.1 C500.1 C501.1 C502.1 C503.1 C504.1 C505.1 C506.1 C507.1 C508.1 C509.1 C510.1 C511.1 C512.1 C513.1 C514.1 C515.1 C516.1 C517.1 C518.1 C519.1 C520.1 C521.1 C522.1 C523.1 C524.1 C525.1 C526.1 C527.1 C528.1 C529.1 C530.1 C531.1 C600.1 C601.1 C602.1 C603.1 C604.1 C605.1 C606.1 C607.1 C608.2 C609.1 C610.1 C611.1 C612.2 C613.1 C615.1 C617.1 C618.1 C700.1 C701.1 C702.1 C703.1 C800.1 C801.1 C802.1 C803.1 C804.1 C806.1 C807.1 C810.1 C850.1 C851.1 C852.1 C900.1 C920.1 C921.1 C922.1 C923.1 C924.1 C925.1 D602.2 D604.2 D605.2 D606.2 D607.2 D609.3 GND.1 IC920.2 J300.1 J303.17 J303.18 J304.9 J304.10 J304.11 J304.12 J304.13 J304.14 J304.15 J304.16 J307.9 J307.10 J307.11 J307.12 J307.13 J307.14 J307.15 J307.16 J308.13 J308.14 J309.13 J309.14 J310.2 J311.2 J312.2 Q601.S Q602.S R204_1.1 R204_2.1 R205_1.1 R205_2.1 R604.1 R605.1 R638.2 R643.2 R704.2 R705.2 R706.2 R707.2 R708.2 R709.2 R710.2 R711.2 R712.2 R713.2 R804.1 R808.1 R809.1 R810.2 R854.1 R917.1 R918.1 R919.1 R921.1 R922.1 R923.1 R924.1 R925.1 R926.1 R927.1 R928.1 R929.1 R930.1 R931.1 R932.1 R933.1 U200_1.4 U200_2.4 U201_1.14 U201_2.14 U202_1.2 U202_2.2 U400.1 U400.2 U400.4 U600.43 U600.58 U600.59 U600.62 U600.63 U600.64 U600.65 U601.3 U800.1 U800.9 U850.4 U850.9 U851.4 U851.9 U900.2 U900.12 U900.21 U920.1 U920.5 U920.7 U921.2 U921.7 U921.8 U921.9 U922.1 U922.7 | length 8188.5
  Top Copper w8: U920.5@359.65,2736.61 345.8,2736.61 344.92,2737.5 v2(312.5,2737.5) 330.86,2755.86 330.86,2761.96 356.69,2787.8 U920.7@359.65,2787.8 ; U920.1@440.35,2813.39 454.2,2813.39 455.08,2812.5 v2(487.5,2812.5)
  Top Copper w12: U922.7@490.75,2559.74 490.75,2534.25 522.24,2502.76 U922.1@522.24,2465.26 558.6,2465.26 577.3,2483.96 C923.1@600,2483.96 ; C924.1@578.54,2375 578.54,2443.74 600,2465.19 C923.1@600,2483.96 ; U921.2@646.06,2765.16 709.84,2765.16 v2(725,2750) ; v1(750,2483.96) C923.1@600,2483.96 ; v1(1234.84,2125) U900.12@1284.84,2125 ; v1(1234.84,2380.91) U900.2@1284.84,2380.91 ; C900.1@1467.91,2490.75 v1(1467.91,2524.7) ; U900.21@1525,2329.72 v1(1575,2329.72) ; R604.1@3052.56,2775 v1(3080.45,2775) ; v1(3075,1725) 3075,1741.24 ; v1(3075,1850) v1@3076.69,1850 ; U600.64@3156.59,1741.24 3075,1741.24 ; U600.63@3156.59,1760.93 3075,1760.93 ; U600.62@3156.59,1780.61 3080.61,1780.61 3075,1775 3075,1760.93 ; U600.59@3156.59,1839.67 3087.03,1839.67 v1@3076.69,1850 ; U600.58@3156.59,1859.35 3087.5,1859.35 3078.14,1850 v1@3076.69,1850 ; C612.2@4671.06,1575 v1(4671.06,1625) ; v1(4682.05,2087.5) R810.2@4709.94,2087.5 ; D607.2@4728.15,1715.06 v1(4728.15,1742.95) ; C610.1@4807.15,1720.08 C610.1@4807.15,1728.54 v1(4807.15,1747.97) ; v1(4812.5,2000) C810.1@4858.37,2000 ; R808.1@4862.5,2140.06 v1(4862.5,2167.95) ; v1(4875,2325) C801.1@4936.91,2325 ; v1(4875,2562.5) C800.1@4936.91,2562.5 ; D606.2@4886.15,1715.06 v1(4886.15,1742.95) ; C609.1@4943.24,1575 v1(4943.24,1625) ; v1(5050,2286.78) R809.1@5050,2314.67 ; U800.9@5200,2325 v1(5287.5,2325) ; U800.1@5275,2432.28 v1(5275,2475) ; C608.2@5296.06,1575 v1(5296.06,1625) ; D605.2@5353.15,1715.06 v1(5353.15,1742.95) ; C607.1@5432.15,1720.08 C607.1@5432.15,1728.54 v1(5432.15,1747.97) ; D604.2@5511.15,1715.06 v1(5511.15,1742.95) ; C807.1@5525.59,2125 v1(5562.5,2125) ; C806.1@5555.12,2237.5 v1(5600,2237.5) ; C803.1@5555.12,2362.5 v1(5600,2362.5) ; C802.1@5555.12,2487.5 v1(5600,2487.5) ; C602.1@5568.24,1575 v1(5568.24,1625) ; v1(5587.5,2712.5) C804.1@5639.27,2712.5 ; R804.1@5687.5,2009.94 5722.44,2009.94 v1@5723.72,2011.22 ; Q602.S@5897.24,1689.86 v1(5897.24,1717.75) ; C618.1@6015.16,1675 v1(6043.05,1675) ; R643.2@6030.12,1725 v1(6058.01,1725) ; C617.1@6050,1616.04 v1(6050,1643.93) ; 3075,1741.24 3075,1760.93
  Top Copper w15: U201_2.14@784.84,1736.61 v2(844.69,1736.61) ; U201_1.14@1934.84,1736.61 v2(1994.69,1736.61)
  Top Copper w16: v1(275,2662.5) C920.1@275,2696.46 ; C921.1@275,2878.54 v1(275,2912.5) ; C201_2.1@357.09,862.5 v1@387.3,862.5 ; C200_2.1@357.09,925 v1@387.3,925 ; C202_2.1@400,803.54 v1@400,833.76 ; U200_2.4@400,993.7 v1@430.22,993.7 ; v1(413.29,2962.5) IC920.2@447.24,2962.5 ; C211_2.1@487.01,1128.54 v1@487.01,1158.76 ; C219_2.1@487.01,1390.35 v1@487.01,1424.51 ; v1@487.01,1625.79 R204_2.1@487.01,1659.94 ; C925.1@525,3003.54 v1(525,3037.5) ; C210_2.1@605,1128.54 v1@605,1158.76 ; C218_2.1@605,1390.35 v1@605,1424.51 ; v1@605,1625.79 R205_2.1@605,1659.94 ; C922.1@628.54,2875 v1(662.5,2875) ; C209_2.1@722.99,1128.54 v1@722.99,1158.76 ; C217_2.1@722.99,1390.35 v1@722.99,1424.51 ; C203_2.1@778.54,1625 v1@812.7,1625 ; C208_2.1@840.98,1128.54 v1@840.98,1158.76 ; C216_2.1@840.98,1390.35 v1@840.98,1424.51 ; v1(843.41,2090.75) R926.1@877.36,2090.75 ; v1(843.41,2153.25) R919.1@877.36,2153.25 ; v1(843.41,2215.75) R930.1@877.36,2215.75 ; v1(843.41,2278.25) R925.1@877.36,2278.25 ; v1(843.41,2340.75) R918.1@877.36,2340.75 ; v1(843.41,2403.25) R929.1@877.36,2403.25 ; v1(843.41,2465.75) R924.1@877.36,2465.75 ; v1(843.41,2528.25) R917.1@877.36,2528.25 ; C207_2.1@959.02,1128.54 v1@959.02,1158.76 ; C215_2.1@959.02,1390.35 v1@959.02,1424.51 ; C214_2.1@1075,1390.35 v1@1075,1424.51 ; C206_2.1@1077.01,1128.54 v1@1077.01,1158.76 ; v1@1118.6,1621.46 C220_2.1@1152.76,1621.46 ; C205_2.1@1195,1128.54 v1@1195,1158.76 ; C213_2.1@1195,1390.35 v1@1195,1424.51 ; v1(1195,1625) C221_2.1@1232.28,1625 ; U202_2.2@1247.24,1787.5 1325,1787.5 v1(1350,1812.5) ; v1@1312.5,1425 1312.99,1424.51 C212_2.1@1312.99,1390.35 ; C204_2.1@1312.99,1128.54 v1@1312.99,1158.76 ; v2(1450,3125) C700.1@1483.96,3125 1483.96,3171.46 v2(1487.5,3175) ; C201_1.1@1507.09,862.5 v1@1537.3,862.5 ; C200_1.1@1507.09,925 v1@1537.3,925 ; C202_1.1@1550,803.54 v1@1550,833.76 ; U200_1.4@1550,993.7 v1@1580.22,993.7 ; C211_1.1@1637.01,1128.54 v1@1637.01,1158.76 ; C219_1.1@1637.01,1390.35 v1@1637.01,1424.51 ; v1@1637.01,1625.79 R204_1.1@1637.01,1659.94 ; C210_1.1@1755,1128.54 v1@1755,1158.76 ; C218_1.1@1755,1390.35 v1@1755,1424.51 ; v1@1755,1625.79 R205_1.1@1755,1659.94 ; C701.1@1841.04,3125 v2(1875,3125) ; C209_1.1@1872.99,1128.54 v1@1872.99,1158.76 ; C217_1.1@1872.99,1390.35 v1@1872.99,1424.51 ; C203_1.1@1928.54,1625 v1@1962.7,1625 ; R931.1@1932.48,2103.25 v1(1966.44,2103.25) ; R921.1@1932.48,2165.75 v1(1966.44,2165.75) ; R927.1@1932.48,2228.25 v1(1966.44,2228.25) ; R932.1@1932.48,2290.75 v1(1966.44,2290.75) ; R922.1@1932.48,2353.25 v1(1966.44,2353.25) ; R928.1@1932.48,2415.75 v1(1966.44,2415.75) ; R933.1@1932.48,2478.25 v1(1966.44,2478.25) ; R923.1@1932.48,2540.75 v1(1966.44,2540.75) ; C208_1.1@1990.98,1128.54 v1@1990.98,1158.76 ; C216_1.1@1990.98,1390.35 v1@1990.98,1424.51 ; v1(2012.5,2975) C850.1@2062.5,2975 ; v1(2025,2513.19) C851.1@2025,2547.15 ; C207_1.1@2109.02,1128.54 v1@2109.02,1158.76 ; C215_1.1@2109.02,1390.35 v1@2109.02,1424.51 ; v1(2125,2100) U400.4@2168.7,2100 ; v1(2125,2200) U400.2@2168.7,2200 ; v1(2125,2250) U400.1@2168.7,2250 ; U850.4@2188.39,2674.9 v1(2223.33,2674.9) ; C852.1@2194.29,2962.5 v1(2225,2962.5) ; v1(2202.76,2325) C400.1@2246.46,2325 ; C214_1.1@2225,1390.35 v1@2225,1424.51 ; C206_1.1@2227.01,1128.54 v1@2227.01,1158.76 ; v1@2268.6,1621.46 C220_1.1@2302.76,1621.46 ; C205_1.1@2345,1128.54 v1@2345,1158.76 ; C213_1.1@2345,1390.35 v1@2345,1424.51 ; v1(2345,1625) C221_1.1@2382.28,1625 ; U202_1.2@2397.24,1787.5 2475,1787.5 v1(2500,1812.5) ; v1@2462.5,1425 2462.99,1424.51 C212_1.1@2462.99,1390.35 ; C204_1.1@2462.99,1128.54 v1@2462.99,1158.76 ; v1@2675,514.67 R605.1@2675,544.88 ; C600.1@2712.5,1567.72 v1(2712.5,1601.67) ; v1(2725,1037.5) C500.1@2725,1071.46 ; C501.1@2725,1378.54 v1(2725,1412.5) ; v1(2725,1709.25) C603.1@2725,1743.21 ; v1(2800,1709.25) C604.1@2800,1743.21 ; v1(2825,1037.5) C504.1@2825,1071.46 ; C505.1@2825,1378.54 v1(2825,1412.5) ; v1@2875,1719 C605.1@2875,1743.21 ; v1(2925,1037.5) C508.1@2925,1071.46 ; C509.1@2925,1378.54 v1(2925,1412.5) ; v1(2950,1709.25) C606.1@2950,1743.21 ; D602.2@2962.5,1667.62 3021.48,1667.62 3022.51,1668.65 v1@3022.51,1670.11 ; v1@3023.92,1708.71 3025,1709.79 C613.1@3025,1743.21 ; v1(3025,1037.5) C512.1@3025,1071.46 ; C513.1@3025,1378.54 v1(3025,1412.5) ; C601.1@3037.5,1567.72 v1(3037.5,1601.67) ; v1(3125,1037.5) C516.1@3125,1071.46 ; C517.1@3125,1378.54 v1(3125,1412.5) ; C611.1@3125,2400.59 v1(3125,2437.5) ; v1(3225,1037.5) C520.1@3225,1071.46 ; C521.1@3225,1378.54 v1(3225,1412.5) ; v1(3325,1037.5) C524.1@3325,1071.46 ; C525.1@3325,1378.54 v1(3325,1412.5) ; U600.43@3333.76,2115.26 3333.76,2053.74 v1@3337.5,2050 ; v1(3425,1037.5) C528.1@3425,1071.46 ; C529.1@3425,1378.54 v1(3425,1412.5) ; v1(3525,1037.5) C502.1@3525,1071.46 ; C503.1@3525,1378.54 v1(3525,1412.5) ; v1(3625,1037.5) C506.1@3625,1071.46 ; C507.1@3625,1378.54 v1(3625,1412.5) ; v1(3725,1037.5) C510.1@3725,1071.46 ; C511.1@3725,1378.54 v1(3725,1412.5) ; C530.1@3812.5,804.53 v1(3812.5,838.48) ; v1(3825,1037.5) C514.1@3825,1071.46 ; C515.1@3825,1378.54 v1(3825,1412.5) ; v1(3925,1037.5) C518.1@3925,1071.46 ; C519.1@3925,1378.54 v1(3925,1412.5) ; C531.1@3950,745.47 v1(3950,711.52) 3988.48,711.52 GND.1@4025,675 ; v1(4025,1037.5) C522.1@4025,1071.46 ; C523.1@4025,1378.54 v1(4025,1412.5) ; v1(4109.25,1065.55) 4110.71,1067.01 4120.55,1067.01 C526.1@4125,1071.46 ; C527.1@4125,1378.54 v1(4125,1412.5) ; v1(4387.6,1063.29) Q601.S@4387.6,1097.24 4387.6,1137.6 4397.44,1147.44 R638.2@4397.44,1175 4397.44,1196.72 4404.92,1204.2 C615.1@4404.92,1250 v1(4404.92,1283.96) ; v2(4400,3125) C703.1@4433.96,3125 ; v1(4425,793.8) D609.3@4425,827.76 ; v2(4787.5,3175) 4791.04,3171.46 C702.1@4791.04,3125 v2(4825,3125) ; v1(5925,1550) 5925,1514.41 6040.75,1398.66 U601.3@6040.75,1337.99
  Top Copper w24: v1(2223.33,2674.9) 2223.43,2675 R854.1@2259.94,2675
  GND w24: J310.2@4050,1675 4137.5,1675 ; 4200,2675 J311.2@4300,2675 ; 5687.5,2675 J312.2@5787.5,2675
  other v1: 2675,514.17 400,834.25 1550,834.25 387.8,862.5 1537.8,862.5 387.8,925 1537.8,925 430.71,993.7 1580.71,993.7 487.01,1159.25 605,1159.25 722.99,1159.25 840.98,1159.25 959.02,1159.25 1077.01,1159.25 1195,1159.25 1312.99,1159.25 1637.01,1159.25 1755,1159.25 1872.99,1159.25 1990.98,1159.25 2109.02,1159.25 2227.01,1159.25 2345,1159.25 2462.99,1159.25 487.01,1425 605,1425 722.99,1425 840.98,1425 959.02,1425 1075,1425 1195,1425 1312.99,1425 1637.01,1425 1755,1425 1872.99,1425 1990.98,1425 2109.02,1425 2225,1425 2345,1425 2462.99,1425 1118.11,1621.46 2268.11,1621.46 487.01,1625.3 605,1625.3 813.19,1625 1637.01,1625.3 1755,1625.3 1963.19,1625 3025,1667.62 2875,1709.25 3025,1709.25 5725,2009.94 3333.76,2050 5112.5,2287.5 5112.5,2325 5112.5,2362.5 5287.5,2362.5 1939.27,2737.5 2062.5,2737.5 2100,2737.5 2200,2737.5 1939.27,2762.5 2062.5,2762.5 2100,2762.5 2200,2762.5 1939.27,2787.5 2062.5,2787.5 2100,2787.5 2200,2787.5
  other v2: 3274.7,1780.61 3318.01,1780.61 3361.32,1780.61 3404.63,1780.61 3447.93,1780.61 3491.24,1780.61 3274.7,1823.92 3318.01,1823.92 3361.32,1823.92 3404.63,1823.92 3447.93,1823.92 3491.24,1823.92 3274.7,1867.22 3318.01,1867.22 3361.32,1867.22 3404.63,1867.22 3447.93,1867.22 3491.24,1867.22 3274.7,1910.53 3318.01,1910.53 3361.32,1910.53 3404.63,1910.53 3447.93,1910.53 3491.24,1910.53 3274.7,1953.84 3318.01,1953.84 3361.32,1953.84 3404.63,1953.84 3447.93,1953.84 3491.24,1953.84 3274.7,1997.15 3318.01,1997.15 3361.32,1997.15 3404.63,1997.15 3447.93,1997.15 3491.24,1997.15
Gnd2_unused: U601.8
Gnd22_unused: U601.7
GPIO0: R606.2 R629.2 U600.56 | length 1324.8
  Top Copper w8: 2986.22,1898.72 U600.56@3156.59,1898.72
  Top Copper w12: v1(2818.75,1875) 2842.47,1898.72 2986.22,1898.72
  Top Copper w16: R629.2@2765.06,1875 v1(2818.75,1875) ; R606.2@2765.06,2400 v1(2818.75,2400)
  Signal Layer 1 w16: v1(2818.75,1875) 3062.5,2118.75 v1(3062.5,2400)
  Signal Layer 2 w16: v1(2818.75,2400) v1(3062.5,2400)
GPIO1: R607.2 R630.2 U600.55 | length 1269.8
  Top Copper w8: v1(3002.34,1922.53) 3052.47,1922.53 3056.59,1918.41 U600.55@3156.59,1918.41
  Top Copper w16: R630.2@2765.06,1937.5 v1(2818.75,1937.5) ; R607.2@2765.06,2462.5 v1(2818.75,2462.5)
  Signal Layer 1 w16: v1(2818.75,1937.5) 3025,2143.75 v1(3025,2462.5)
  Signal Layer 2 w12: v1(2818.75,1937.5) 2833.72,1922.53 v1(3002.34,1922.53)
  Signal Layer 2 w16: v1(2818.75,2462.5) v1(3025,2462.5)
GPIO2: R608.2 R623.2 R631.2 U600.54 | length 1288.9
  Top Copper w8: 3050,1950 3061.91,1938.09 U600.54@3156.59,1938.09
  Top Copper w12: v1(2818.75,2000) 2869.56,1949.19 2973.19,1949.19 2974,1950 3050,1950
  Top Copper w16: R631.2@2765.06,2000 v1(2818.75,2000) R623.2@2872.44,2000 ; R608.2@2765.06,2525 v1(2818.75,2525)
  Signal Layer 1 w16: v1(2818.75,2000) 2987.5,2168.75 v1(2987.5,2525)
  Signal Layer 2 w16: v1(2818.75,2525) v1(2987.5,2525)
GPIO2_ext: J308.1 J309.1 R623.1 | length 5617.2
  Top Copper w12: R623.1@2927.56,2000 2927.56,1996.06 2946.69,1976.93 2960.57,1976.93 v1(2962.5,1975)
  Signal Layer 1 w16: v1(4137.5,1475) v1(4137.5,1562.5)
  Signal Layer 2 w12: J308.1@4575,2075 4658.05,2075 4671.36,2061.69 4747.47,2061.69 4749.09,2063.31 4824.68,2063.31 4828.86,2059.13 4904.44,2059.13 4933.62,2088.31 4987.06,2088.31 4989.31,2086.06 5560.07,2086.06 5593.45,2119.45 6018.05,2119.45 J309.1@6062.5,2075
  Signal Layer 2 w16: v1(2887.5,1475) v1(4137.5,1475) ; v1(4462.5,1562.5) v1(4600,1562.5)
  Bot Copper w16: v1(2887.5,1475) 2875,1487.5 2875,1669.92 2922.19,1717.11 2922.19,1934.69 v1(2962.5,1975) ; v1(4137.5,1562.5) v1(4462.5,1562.5) ; v1(4600,1562.5) 4615.31,1547.19 5009.69,1547.19 5290.72,1828.22 5815.72,1828.22 J309.1@6062.5,2075
GPIO3: R613.2 R624.2 R633.2 U600.53 | length 1389.2
  Top Copper w8: v1(3037.5,1975.81) 3061.69,1975.81 3079.72,1957.78 U600.53@3156.59,1957.78
  Top Copper w16: R633.2@2765.06,2062.5 v1(2818.75,2062.5) R624.2@2872.44,2062.5 ; R613.2@2765.06,2775 2862.5,2775 2950,2687.5 v1(2950,2587.5)
  Signal Layer 1 w16: v1(2818.75,2062.5) 2950,2193.75 v1(2950,2587.5)
  Signal Layer 2 w12: v1(2818.75,2062.5) 2868.75,2012.5 2961.5,2012.5 2998.19,1975.81 v1(3037.5,1975.81)
GPIO3_ext: J308.2 J309.2 R624.1 | length 5796.7
  Top Copper w12: R624.1@2927.56,2062.5 2927.56,2058.56 2973.62,2012.5 v1(3000,2012.5)
  Signal Layer 1 w16: v1(4175,1475) v1(4175,1600)
  Signal Layer 2 w12: J308.2@4475,2075 4538.31,2011.69 4775.75,2011.69 4789.87,2025.81 4967.97,2025.81 5009.65,1984.13 5485.69,1984.13 5576.56,2075 J309.2@5962.5,2075
  Signal Layer 2 w16: v1(2837.5,1462.5) 2852.81,1447.19 4149.02,1447.19 4175,1473.17 v1(4175,1475) ; v1(4462.5,1600) 4643.75,1600 4668.75,1575 v1(4850,1575)
  Bot Copper w16: v1(2837.5,1462.5) 2837.5,1711.08 2865.31,1738.89 2865.31,1917.14 2960.67,2012.5 v1(3000,2012.5) ; v1(4175,1600) v1(4462.5,1600) ; v1(4850,1575) 5009.22,1575 5282.43,1848.22 5735.72,1848.22 J309.2@5962.5,2075
GPIO4: R615.2 R635.2 U600.52 | length 1163.9
  Top Copper w8: 3037.5,2025 3085.04,1977.46 U600.52@3156.59,1977.46
  Top Copper w12: v1(2818.75,2125) 2937.5,2125 3037.5,2025
  Top Copper w16: R635.2@2765.06,2125 v1(2818.75,2125) ; R615.2@2765.06,2650 v1(2818.75,2650)
  Signal Layer 1 w16: v1(2818.75,2125) 2912.5,2218.75 v1(2912.5,2650)
  Signal Layer 2 w16: v1(2818.75,2650) v1(2912.5,2650)
GPIO5: R620.2 R636.2 U600.51 | length 1128.6
  Top Copper w8: 3050,2044.16 3097.02,1997.15 U600.51@3156.59,1997.15
  Top Copper w12: v1(2818.75,2187.5) 2906.66,2187.5 3050,2044.16
  Top Copper w16: R636.2@2765.06,2187.5 v1(2818.75,2187.5) ; R620.2@2765.06,2712.5 v1(2818.75,2712.5)
  Signal Layer 1 w16: v1(2818.75,2187.5) 2875,2243.75 v1(2875,2712.5)
  Signal Layer 2 w16: v1(2818.75,2712.5) v1(2875,2712.5)
GPIO6: R609.2 R625.2 R639.2 U600.50 | length 904.7
  Top Copper w8: 3043.5,2075 3101.67,2016.83 U600.50@3156.59,2016.83
  Top Copper w12: R625.2@2872.44,2250 2872.44,2246.06 3043.5,2075
  Top Copper w16: R639.2@2765.06,2250 R625.2@2872.44,2250 ; R609.2@2765.06,2587.5 v1(2818.75,2587.5)
  Signal Layer 1 w16: v1(2818.75,2250) 2790.94,2277.81 2790.94,2559.69 v1(2818.75,2587.5)
GPIO6_ext: J308.3 J309.3 R625.1 | length 3757.4
  Top Copper w12: v1(5837.5,2149.19) 5861.69,2125 6012.5,2125 J309.3@6062.5,2175
  Top Copper w16: R625.1@2927.56,2250 2927.56,2246.06 3070.73,2102.89 3070.73,2088.96 v1(3072.19,2087.5)
  Signal Layer 2 w12: J308.3@4575,2175 4833.05,2175 4901.58,2243.53 5342.97,2243.53 5435.69,2150.81 5835.88,2150.81 v1(5837.5,2149.19)
  Signal Layer 2 w16: v1(3400,2450) v1(4325,2450)
  Bot Copper w16: v1(3072.19,2087.5) 3072.19,2286.52 3250.98,2465.31 3384.69,2465.31 v1(3400,2450) ; v1(4325,2450) 4325,2359.31 4462.86,2221.45 4528.55,2221.45 J308.3@4575,2175
GPIO7: R614.2 R626.2 R640.2 U600.49 | length 1249.1
  Top Copper w8: 3100,2050 3113.48,2036.52 U600.49@3156.59,2036.52
  Top Copper w16: R640.2@2765.06,2312.5 v1(2818.75,2312.5) R626.2@2872.44,2312.5 ; R614.2@2765.06,2837.5 v1(2818.75,2837.5) ; 3100,2050 v1(3100,2200)
  Signal Layer 1 w16: v1(2818.75,2312.5) 2818.75,2360.67 2846.56,2388.48 2846.56,2809.69 v1(2818.75,2837.5)
  Signal Layer 2 w16: v1(2818.75,2312.5) 2987.5,2312.5 v1(3100,2200)
GPIO7_ext: J308.4 J309.4 R626.1 | length 3290.8
  Top Copper w16: R626.1@2927.56,2312.5 3062.5,2312.5 v1(3100,2275)
  Signal Layer 2 w12: J308.4@4475,2175 4530.55,2230.55 4865.97,2230.55 4894.95,2259.53 5378.76,2259.53 5463.29,2175 J309.4@5962.5,2175
  Signal Layer 2 w16: v1(3337.5,2375) 3365.31,2402.81 4282.63,2402.81 4285.44,2400 v1(4287.5,2400)
  Bot Copper w16: v1(3100,2275) 3100,2276.83 3198.17,2375 v1(3337.5,2375) ; v1(4287.5,2400) 4287.5,2362.5 J308.4@4475,2175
